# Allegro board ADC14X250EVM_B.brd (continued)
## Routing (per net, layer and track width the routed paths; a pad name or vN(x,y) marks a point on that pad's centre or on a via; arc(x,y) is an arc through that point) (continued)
GND2: length 14.7
  TOP w0.305: U7.3 16.79,7.83 v1(16.46,8.16)
  TOP w0.381: v1(27.44,12.36) 27.44,12.36 C86.2 C158.2 ; v1(24.68,13.48) 24.56,13.6 C84.2 ; v1(28.97,7.07) 28.55,7.07 28.37,7.25 J9.5 28.37,8.86 28.49,8.98 v1(28.95,8.98)
  BOTTOM w0.381: U6.25 20.2,13.42 v1(19.87,13.75) 19.55,13.42 U6.26 ; U6.21 22.8,10.94 v1(22.77,10.91) 22.61,10.76 C161.2 ; v1(24.68,13.48) 24.75,13.42 U6.18 ; U6.7 v1(22.15,17.76)
  BOTTOM w0.457: C162.2 v1(20.25,22.42)
  vias: v1(6.93,11.35) v1(8.34,10.82) v1(8.35,9.51) v1(10.34,10.85) v1(10.36,9.61) v1(11.46,10.95) v1(11.46,10.22) v1(12.74,10.97) v1(12.74,10.24) v1(15.82,8.18) v1(18.88,14.09) v1(20.82,14.11) v1(21.59,8.84) v1(21.62,7.05) v1(21.62,3.32) v1(21.65,1.53) v1(23.01,8.86) v1(23.02,7.04) v1(23.03,3.34) v1(23.05,1.52) v1(26.51,1.88) v1(30.51,8.84) v1(30.53,7.05) v1(30.52,3.37) v1(30.55,1.57) v1(31.92,8.86) v1(31.94,7.05) v1(31.93,3.38) v1(31.95,1.57) v2(0.91,22.91) v2(0.91,17.83) v2(0.91,12.75) v2(0.91,7.67) v2(0.91,2.59) v2(3.45,22.91) v2(5.83,12.74) v2(5.99,22.91) v2(5.99,17.83) v2(8.53,22.91) v2(11.07,22.91) v2(11.07,17.83) v2(11.07,2.59) v2(11.97,16.38) v2(11.97,15.16) v2(12.45,22.86) v2(12.45,21.97) v2(12.67,16.38) v2(12.67,15.16) v2(13.03,22.43) v2(13.61,22.91) v2(13.72,21.97) v2(13.96,3.85) v2(16.15,22.91) v2(16.15,17.83) v2(16.15,2.59) v2(22.1,15.32) v2(26.75,22.91) v2(27.18,15.32) v2(28.09,22.91) v2(30.56,22.91) v2(33.1,22.91) v2(33.53,20.4) v2(33.53,17.86) v2(33.53,15.32) v2(33.53,12.78) v2(33.53,10.24) v2(33.53,7.7) v2(33.53,5.16) v2(33.53,2.62)
VIN+: length 1.8
  TOP w0.203: U1.3 44.88,78.86 44.87,78.87 R24.2
VIN-: length 1.8
  TOP w0.203: U1.4 44.88,78.36 44.87,78.34 R25.2
VINN: length 2
  TOP w0.33: R15.2 R4.2 9.78,77.34 T1.4
VINN+: length 20.2
  TOP w0.203: R7.1 43,78.87 R24.1
  TOP w0.33: R7.1 42.82,79.1 42.3,79.63 arc(42.19,79.7) 42.07,79.72 C17.1 39.29,79.71 arc(38.99,79.65) 38.74,79.48 38.49,79.24 C19.1 38.11,79.11 arc(37.87,79.16) 37.67,79.3 37.47,79.5 arc(37.05,79.78) 36.56,79.88 R3.2
VINN-: length 20.2
  TOP w0.203: R9.1 43,78.34 R25.1
  TOP w0.33: R9.1 42.82,78.11 42.3,77.58 arc(42.19,77.51) 42.07,77.49 C23.1 arc(39,77.55) 38.73,77.72 38.49,77.97 C19.2 38.22,78.1 arc(37.89,78.03) 37.61,77.85 37.54,77.77 arc(37.05,77.45) 36.48,77.34 R10.2
VINP: length 2
  TOP w0.33: T1.6 9.78,79.88 R14.1 R11.2
ADC_CSB: length 120.8
  TOP w0.203: v3(57.4,96.27) 57.52,92.14 53.42,88.04 53.42,81.06 51.71,79.35 51.22,79.35 U1.23 ; R85.1 24.8,22.24 R83.1 v1(28.47,29.84)
  BOTTOM w0.203: R95.2 58.31,95.63 57.88,96.06 57.61,96.06 v3(57.4,96.27) 56.39,95.25 47.88,95.25 47.5,95.63 R77.2 47.37,95.58 46.53,94.74 42.04,94.74 30.81,83.52 30.8,83.52 29.18,81.89 28.59,81.89 26.06,79.36 26.06,69.7 29.2,66.56 29.2,30.58 v1(28.47,29.84)
ADC_SCLK: length 31.1
  TOP w0.203: U1.24 51.5,79.86 52.83,81.18 52.83,95.26 v3(54.98,97.41)
  BOTTOM w0.203: R92.2 58.88,97.46 58.51,97.82 56.42,97.82 56.01,97.41 v3(54.98,97.41) R70.2
ADC_SDI: length 30.8
  TOP w0.203: v3(51.27,98.42) 51.27,86.68 52.25,85.7 52.25,81.85 50.98,80.58 U1.25
  BOTTOM w0.203: R93.1 v3(51.27,98.42) R73.2
ADC_SDO: length 30.3
  TOP w0.203: U1.26 49.99,80.97 50.12,81.1 50.26,81.23 50.9,81.23 51.66,82 51.66,84.28 48.73,87.21 v3(48.73,96.39)
  BOTTOM w0.203: R94.1 58.88,96.44 58.06,97.26 56.74,97.26 55.88,96.39 v3(48.73,96.39) R72.2
BP2P5: length 25.5
  TOP w0.305: TP14.1 64.98,89.71 59.24,83.98 59.24,81.43 57.31,79.5 v1(57.28,79.5) C44.1 52.94,79.5 52.66,79.22 C43.1 52.15,79.22 51.78,78.86 U1.22
  BOTTOM w0.381: v1(57.28,79.5) 57.4,79.38 C45.1
CLKIN+: length 15.6
  TOP w0.203: v1(45.6,60.63) R18.2 45.79,61.41 45.79,62.88 46.56,63.64 46.56,74.57 46.99,75 U1.9
CLKIN-: length 15.6
  TOP w0.203: v1(46.31,60.63) R18.1 46.2,61.32 46.2,62.71 46.97,63.48 46.97,74.4 47.49,74.92 U1.10
CLKOUT2+: length 31.5
  TOP w0.203: U13.15 68.62,41.87 68.33,41.87 68.28,41.82 66.81,41.82 66.18,41.19 65.9,41.19 v1(65.71,41.38)
  BOTTOM w0.203: C71.1 46.14,57.9 46.14,57 62.02,41.12 64.9,41.12 65.08,41.3 65.08,41.57 65.26,41.76 65.53,41.76 65.71,41.57 v1(65.71,41.38)
CLKOUT2-: length 31.5
  TOP w0.203: U13.16 68.62,41.36 68.33,41.36 68.28,41.41 66.98,41.41 66.35,40.78 65.88,40.78 v1(65.71,40.62)
  BOTTOM w0.203: v1(65.71,40.62) 65.61,40.72 61.85,40.72 45.74,56.83 45.74,57.92 C70.1
CLKOUT3+: length 31.5
  TOP w0.203: v1(65.71,43.61) 65.88,43.45 66.35,43.45 66.98,42.82 68.28,42.82 68.31,42.86 68.62,42.86 U13.13
  BOTTOM w0.203: C69.1 49.56,57.89 49.56,57.33 49.89,57 53.75,57 54.19,56.56 54.19,55.33 53.75,54.89 52.88,54.89 52.55,54.56 52.55,53.62 62.82,43.36 64.94,43.36 65.08,43.5 65.08,43.79 65.26,43.98 65.54,43.98 65.71,43.81 v1(65.71,43.61)
CLKOUT3-: length 31.5
  TOP w0.203: U13.14 68.62,42.37 68.31,42.37 68.28,42.41 66.81,42.41 66.18,43.04 65.9,43.04 v1(65.71,42.85)
  BOTTOM w0.203: C68.1 49.15,57.94 49.15,57.16 49.72,56.59 53.58,56.59 53.78,56.39 53.78,55.5 53.58,55.3 52.71,55.3 52.14,54.73 52.14,53.46 62.65,42.95 65.61,42.95 v1(65.71,42.85)
CLKOUT4+: length 1.8
  TOP w0.203: v1(72.63,39.05) 72.81,39.23 72.81,40.38 72.76,40.43 72.76,40.72 U13.24
CLKOUT4-: length 1.8
  TOP w0.203: U13.25 73.27,40.72 73.27,40.43 73.22,40.38 73.22,39.23 v1(73.39,39.05)
CLKOUT8+: length 3.5
  TOP w0.203: R165.1 76.72,52.36 76.72,51.63 75.72,50.62 75.72,49.85 75.76,49.82 75.76,49.51 U13.51
CLKOUT8-: length 3.5
  TOP w0.203: U13.52 75.27,49.51 75.27,49.82 75.31,49.85 75.31,50.79 76.31,51.79 76.31,52.33 R164.1
CLKOUT10+: length 3.5
  TOP w0.203: R163.1 74.22,52.75 74.22,49.85 74.26,49.82 74.26,49.51 U13.54
CLKOUT10-: length 3.5
  TOP w0.203: U13.55 73.77,49.51 73.77,49.82 73.81,49.85 73.81,52.75 R162.1
CLKOUT11+: length 3.5
  TOP w0.203: R161.1 72.21,52.33 72.21,51.79 73.22,50.79 73.22,49.85 73.27,49.8 73.27,49.51 U13.56
CLKOUT11-: length 3.5
  TOP w0.203: R160.1 71.81,52.36 71.81,51.63 72.81,50.62 72.81,49.85 72.76,49.8 72.76,49.51 U13.57
CSB_LMK_3P3: length 24.3
  TOP w0.203: U13.18 69.76,40.72 69.76,39.67 67.31,37.22 67.31,23.11 64.44,20.24 R57.2
EXT_CLK+: length 14.1
  TOP w0.203: R40.1 45.76,59.45 45.76,57.04 41.09,52.38 41.09,51.51 40.05,50.46 T3.4
EXT_CLK-: length 14.1
  TOP w0.203: R41.1 46.16,59.47 46.16,56.88 41.5,52.21 41.5,51.58 42.59,50.49 T3.6
EXT_REF: length 34.3
  TOP w0.33: R35.2 R34.1 80.09,5.21 81.43,3.87 J7.1
EXT_SYSREF+: length 14.1
  TOP w0.203: R44.1 49.17,59.47 49.17,56.95 53.82,52.29 53.82,51.73 52.75,50.65 T4.4
EXT_SYSREF-: length 14.1
  TOP w0.203: R45.1 49.57,59.45 49.57,57.12 54.23,52.46 54.23,51.5 55.29,50.44 T4.6
EXTREF: length 35.3
  TOP w0.33: R17.2 v1(46.35,35.73)
  BOTTOM w0.33: R227.2 78.23,35.76 75.87,33.4 62.23,33.4 60.54,35.09 46.99,35.09 v1(46.35,35.73)
EXTREF_XO: length 5.9
  TOP w0.33: v1(80.09,35.73) C159.1 R36.2
  BOTTOM w0.33: v1(80.09,35.73) 80,35.81 R227.1
EXTXO:
  vias: v1(81.11,35.73)
FMC_FPGA_DEVCLKA+: length 83.9
  TOP w0.203: v1(109.21,93.6) 109.31,93.7 109.31,94.49 109.9,95.07 116.24,95.07 119.91,91.41 119.91,79.24 117.5,76.83 115.08,74.42 91.43,74.42 76.71,59.7 76.71,53.72 R165.2
  BOTTOM w0.203: J8.D4 v1(109.21,93.6)
FMC_FPGA_DEVCLKA-: length 83.9
  TOP w0.203: v1(110.48,93.6) 110.48,93.37 110.28,93.17 109.9,93.17 109.72,93.34 109.72,94.32 110.07,94.67 116.07,94.67 119.5,91.24 119.5,79.41 114.92,74.83 91.26,74.83 76.3,59.87 76.3,53.72 R164.2
  BOTTOM w0.203: J8.D5 v1(110.48,93.6)
FMC_FPGA_DEVCLKB+: length 83.4
  TOP w0.203: v1(105.4,92.33) 106.97,92.33 107.51,91.79 107.51,89.66 107.82,89.36 116.4,89.36 118.27,87.48 118.27,80.42 114.79,76.94 91.28,76.94 73.34,58.99 73.34,55.63 74.22,54.74 74.22,54.12 R163.2
  BOTTOM w0.203: J8.G6 v1(105.4,92.33)
FMC_FPGA_DEVCLKB-: length 83.4
  TOP w0.203: v1(105.4,91.06) 105.4,91.57 105.76,91.92 106.8,91.92 107.11,91.62 107.11,89.49 107.65,88.95 116.23,88.95 117.87,87.32 117.87,80.59 114.62,77.34 91.11,77.34 72.93,59.16 72.93,55.46 73.81,54.58 73.81,54.12 R162.2
  BOTTOM w0.203: J8.G7 v1(105.4,91.06)
FMC_FPGA_SYSREF+: length 83.4
  TOP w0.203: R161.2 72.22,53.72 72.22,54.19 71.66,54.75 69.48,54.75 69.28,54.94 69.28,55.84 69.48,56.04 71.22,56.04 71.79,56.61 71.79,60.07 91.32,79.6 115.27,79.6 116.33,80.65 116.33,87.25 115.79,87.78 110.76,87.78 109.54,86.56 106.56,86.56 106.25,86.87 106.25,87.12 106.38,87.25 v1(106.67,87.25)
  BOTTOM w0.203: v1(106.67,87.25) J8.G9
FMC_FPGA_SYSREF-: length 83.4
  TOP w0.203: R160.2 71.82,53.72 71.82,54.02 71.49,54.34 69.31,54.34 68.87,54.78 68.87,56.01 69.31,56.44 71.05,56.44 71.38,56.77 71.38,60.24 91.15,80.01 115.11,80.01 115.92,80.82 115.92,87.08 115.62,87.38 110.93,87.38 109.71,86.16 106.39,86.16 105.85,86.7 105.85,87.08 105.68,87.25 v1(105.4,87.25)
  BOTTOM w0.203: J8.G10 v1(105.4,87.25)
LMK_ADC_DEVCLK+: length 0.7
  BOTTOM w0.203: R43.1 45.44,59.46 C70.2
LMK_ADC_DEVCLK-: length 0.7
  BOTTOM w0.203: C71.2 46.46,59.46 R50.1
LMK_ADC_SYSREF+: length 0.7
  BOTTOM w0.203: C68.2 48.87,59.46 R51.1
LMK_ADC_SYSREF-: length 0.7
  BOTTOM w0.203: R61.1 49.89,59.46 C69.2
LMK_CSB: length 52.7
  TOP w0.203: U5.13 62.6,10.68 62.05,10.13 62,10.13 61.19,9.32 v2(57.43,9.32)
  BOTTOM w0.203: R75.2 23.28,25.26 24.56,26.54 25.53,26.54 ; v1(25.53,25.91) 25.53,26.54 ; 25.53,26.54 35.46,26.54 40.74,21.26 41.48,21.26 50.88,11.86 54.89,11.86 v2(57.43,9.32)
LMK_DIR: length 51.5
  TOP w0.203: R74.2 22.53,22.68 v1(22.53,29.08)
  TOP w0.254: v2(60.65,18.85) U5.7
  BOTTOM w0.203: v1(22.53,29.08) 37.8,29.08 48.67,18.21 59.71,18.21 59.84,18.35 R27.2 60.65,18.67 v2(60.65,18.85)
LMK_RESET: length 15.2
  TOP w0.203: U13.5 68.09,46.87 v2(67.99,46.97) ; R112.2 v2(64.08,35.92)
  BOTTOM w0.203: R113.2 v2(64.08,35.92) 64.08,37.62 66.8,40.34 66.8,45.92 67.85,46.97 v2(67.99,46.97)
LMK_RESET_FMC: length 71
  TOP w0.203: v1(105.4,68.2) 104.77,67.56 v2(95.25,67.56)
  BOTTOM w0.203: v2(95.25,67.56) 95.25,40.16 91.77,36.68 78.26,36.68 76.89,35.31 68.07,35.31 67.79,35.03 R113.1
  BOTTOM w0.508: J8.G24 v1(105.4,68.2)
LMK_SCLK: length 54.8
  TOP w0.254: v2(61.3,12.9) U5.11
  BOTTOM w0.203: v2(61.3,12.9) 61.3,13.88 60.67,14.52 49.57,14.52 36.27,27.81 21.08,27.81 18.73,25.46 R71.2
LMK_SDIO: length 48.7
  TOP w0.203: v2(55.5,9.32) 56.24,10.06 61.09,10.06 61.95,10.92 U5.12
  BOTTOM w0.203: R76.2 24.04,23.25 26.06,25.27 34.97,25.27 40.51,19.74 41.25,19.74 41.91,19.08 41.91,18.34 42.6,17.65 44.2,17.65 51.31,10.54 52.4,10.54 53.62,9.32 v2(55.5,9.32)
LMK_SYNC: length 13
  TOP w0.203: U13.6 68.1,46.37 v2(67.99,46.26) ; v2(65.3,35.92) v2(65.3,36.8)
  BOTTOM w0.203: v2(67.99,46.26) 67.39,45.66 67.39,38.89 v2(65.3,36.8) v2(65.3,35.92)
LMK_SYNC_FMC: length 67.9
  TOP w0.203: v1(105.4,66.93) 104.77,66.29 v2(94.44,66.29)
  BOTTOM w0.203: R114.1 76.85,35.92 78.37,37.44 91.36,37.44 94.44,40.51 v2(94.44,66.29)
  BOTTOM w0.508: J8.G25 v1(105.4,66.93)
LMK_VCC1/5/6: length 5.3
  TOP w0.203: 77.72,41.36 77.72,41.36 U13.33 ; v2(67.99,44.46) 68.09,44.36 68.62,44.36 U13.10 ; U13.36 77.41,42.86
  TOP w0.254: v2(77.98,41.33) 77.96,41.36 77.72,41.36 ; 77.41,42.86 v1(77.98,42.86)
  BOTTOM w0.381: L3.1 68.47,45.68 C118.1 C61.1 v2(67.99,44.46) ; v2(77.98,41.33) C160.1 ; v1(77.98,42.86) C199.1
LMK_VCC2: length 1.9
  TOP w0.203: U13.17 69.25,40.72 69.25,40.2 v2(69.15,40.09)
  BOTTOM w0.381: v2(69.15,40.09) C152.1
  BOTTOM w0.559: v2(69.15,40.09) 69.15,39.51 L4.2
LMK_VCC3: length 2.1
  TOP w0.203: U13.21 71.26,40.72 71.26,40.2 v2(71.36,40.09)
  BOTTOM w0.381: C200.1 v2(71.36,40.09)
  BOTTOM w0.559: L9.2 70.79,39.52 v2(71.36,40.09)
LMK_VCC4: length 2.5
  TOP w0.203: 73.77,40.72 U13.26
  TOP w0.254: v2(73.8,40.15) 73.77,40.17 73.77,40.72
  BOTTOM w0.381: v2(73.8,40.15) C201.1
  BOTTOM w0.559: v2(73.8,40.15) 74.04,40.39 L10.2
LMK_VCC7: length 2
  TOP w0.203: v1(77.98,44.36) 77.41,44.36 U13.39
  BOTTOM w0.381: L13.2 78.82,44.36 v1(77.98,44.36) C206.1
LMK_VCC8/10: length 9.4
  TOP w0.203: U13.42 77.41,45.88 ; U13.47 77.41,48.37
  TOP w0.254: 77.41,48.37 v1(77.98,48.37) ; 77.41,45.88 v1(77.98,45.88)
  L4_GND w0.559: v1(77.98,48.37) 78.69,47.66 78.69,46.58 v1(77.98,45.88)
  BOTTOM w0.381: C141.1 C204.1 v1(77.98,45.88) 78.82,45.88 L13.1 ; L5.1 77.98,49.51 v1(77.98,48.37) ; L14.1 78.66,48.37 v1(77.98,48.37) ; C164.1 v1(77.98,48.37)
LMK_VCC9: length 2
  TOP w0.203: v1(77.98,47.35) 77.97,47.37 U13.45
  BOTTOM w0.381: L14.2 78.66,47.35 v1(77.98,47.35) C205.1
LMK_VCC11: length 1.8
  TOP w0.254: U13.53 v1(74.76,50.01)
  BOTTOM w0.381: C202.1 v1(74.76,50.01) 75.41,50.66 L11.2
LMK_VCC12: length 2.4
  TOP w0.203: U13.64 69.25,49.51
  TOP w0.254: 69.25,49.51 v2(69.25,50.09)
  BOTTOM w0.381: C203.1 v2(69.25,50.09)
  BOTTOM w0.559: L12.2 68.1,50.09 v2(69.25,50.09)
PG_C2M: length 14
  TOP w0.203: v1(98.17,101.09) R155.1
  BOTTOM w0.203: v1(98.17,101.09) 100.58,101.09 102.36,99.31 108.58,99.31 J8.D1
PG_M2C: length 10.7
  TOP w0.203: v1(106.68,98.67) 106.04,99.31 R156.2
  BOTTOM w0.203: J8.F1 v1(106.68,98.67)
REFCLK: length 26.9
  TOP w0.33: T5.1 70.47,5.62 68.73,3.87 J6.1
REFCLK+: length 6
  TOP w0.203: C81.2 72.63,35.71 70.47,33.55 T5.6
REFCLK-: length 6
  TOP w0.203: C80.2 73.39,35.71 75.55,33.55 T5.4
SCLK_LMK_3P3: length 28.7
  TOP w0.203: v2(67.94,22.78) 67.94,37.09 70.27,39.41 70.27,40.72 U13.19
  BOTTOM w0.203: v2(67.94,22.78) 67.94,24.54 67.39,25.1 64.72,25.1 62.41,22.78 v2(61.07,22.78)
SDIO_LMK_3P3: length 26.7
  TOP w0.203: v2(68.58,21.51) 68.58,36.96 70.75,39.13 70.75,40.72 U13.20
  BOTTOM w0.203: v2(61.95,21.51) v2(68.58,21.51)
SO+: length 53.5
  TOP w0.203: C37.2 67.27,77.38 81.75,77.38 97.62,93.26 107.97,93.26 109.49,91.73 110.71,91.73 110.91,91.53 110.91,90.89 110.79,90.77 110.49,90.77 110.45,90.81 110.45,91.02 v1(110.48,91.06)
  BOTTOM w0.203: J8.C6 v1(110.48,91.06)
SO-: length 53.5
  TOP w0.203: C36.2 67.27,77.79 81.58,77.79 97.45,93.66 108.14,93.66 109.66,92.14 110.88,92.14 111.32,91.7 111.32,91.31 111.57,91.06 v1(111.75,91.06)
  BOTTOM w0.203: J8.C7 v1(111.75,91.06)
SSYSREF+: length 10.9
  TOP w0.203: C186.2 48.87,70.93 49.04,70.76 49.04,65.69 49.55,65.19 49.55,62.96 49.18,62.59 49.18,61.37 R29.2 v1(49.02,60.63)
SSYSREF-: length 10.9
  TOP w0.203: C187.2 49.62,70.93 49.45,70.76 49.45,65.86 49.96,65.35 49.96,62.79 49.59,62.42 49.59,61.36 R29.1 v1(49.74,60.63)
STATUS_LD1: length 18.9
  TOP w0.203: TP19.1 77.37,23.43 77.37,34.52 75.9,35.99 75.9,40.01 76.26,40.37 76.26,40.72 U13.31
STATUS_LD2: length 5.9
  TOP w0.203: U13.48 77.41,48.88 77.45,48.88 77.83,49.25 77.83,50.52 79.45,52.15 TP18.1
SYNCB+: length 67
  TOP w0.203: v1(105.4,83.44) 105.19,83.44 105.07,83.32 105.07,83.09 105.17,83 106.07,83 106.46,83.39 106.46,84.67 105.99,85.14 92.19,85.14 81.02,73.97 50.51,73.97 50.04,74.44 50.04,75.18 49.99,75.23 U1.15
  BOTTOM w0.203: J8.G12 v1(105.4,83.44)
SYNCB-: length 67
  TOP w0.203: v1(105.4,82.17) 105.4,82.41 105.58,82.59 106.24,82.59 106.87,83.22 106.87,84.83 106.16,85.55 92.02,85.55 80.85,74.38 50.67,74.38 50.45,74.61 50.45,75.18 50.49,75.23 U1.16
  BOTTOM w0.203: J8.G13 v1(105.4,82.17)
SYSREF+: length 3.9
  TOP w0.203: C186.1 48.87,72.24 49.01,72.39 49.01,72.83 49.01,74.77 48.99,74.79 U1.13
SYSREF-: length 3.9
  TOP w0.203: C179.1 49.62,72.24 49.47,72.39 49.47,72.64 49.47,74.77 49.49,74.79 U1.14
T1+: length 1.5
  TOP w0.33: C20.1 T1.1
T1-: length 1.5
  TOP w0.33: C21.1 T1.3
V_VCXO3.3: length 58.4
  TOP w0.559: 90.27,57.62 v2(90.27,57.09) v2(88.29,57.09) 88.29,57.62 ; 90.27,57.62 v2(90.27,58.15) v2(88.29,58.15) 88.29,57.62 ; 90.27,57.62 88.29,57.62 ; 88.29,57.62 C60.1 v2(86.64,57.62) ; TP8.1 Z10.3 v2(92.05,28.97)
  L3_POWER w0.559: 88.29,57.62 v2(86.64,57.62) ; 88.29,57.62 v2(88.29,57.09) v2(90.27,57.09) 90.27,57.62 ; 88.29,57.62 v2(88.29,58.15) v2(90.27,58.15) 90.27,57.62 ; 88.29,57.62 L8.1 90.27,57.62
  L3_POWER w1.27: L8.1 94.46,52.44 TP8.1
  BOTTOM w0.762: L8.1 v2(86.64,57.62)
  BOTTOM w1.27: Z10.3 TP8.1
  vias: v2(93.95,29.33) v2(93.95,28.62) v2(94.97,29.33) v2(94.97,28.62)
V_XO3.3: length 36.3
  TOP w0.559: v2(87.08,33.67) v2(87.08,31.6) 86.67,31.6 ; v2(87.08,33.67) v2(87.08,35.74) 86.67,35.74 ; v2(87.08,33.67) Y1.6 ; 86.67,35.74 v2(86.27,35.74) v2(86.27,33.67) ; 86.67,35.74 Y1.6 ; 86.67,31.6 v2(86.27,31.6) v2(86.27,33.67) ; 86.67,31.6 Y1.6 ; v2(86.27,33.67) Y1.6 ; v2(83.24,17.85) Z9.3
  TOP w1.016: v2(86.27,31.6) 85.66,30.99 v1(85.66,22.9) TP7.1 Z9.3
  BOTTOM w0.381: v1(85.66,22.9) TP7.1
  BOTTOM w1.27: TP7.1 Z9.3
  vias: v2(85.15,18.2) v2(85.15,17.5) v2(86.16,18.2) v2(86.16,17.5)
VA1.2: length 89.2
  TOP w0.102: C99.1 45.94,100.85
  TOP w0.254: v1(43.85,76.67) 43.9,76.67 44.29,76.28 45.02,76.28 45.59,76.85 U1.7
  TOP w0.305: C10.1 49.83,81.97 48.99,81.12 U1.28
  TOP w0.381: v1(49.83,83.74) 49.86,83.72 C9.1 49.86,82.02 C10.1
  TOP w0.635: v1(41.4,75.56) 42.11,75.56 42.29,75.74 C12.1 42.71,75.77 43.24,76.3 43.44,76.3 43.8,76.67 v1(43.85,76.67)
  TOP w1.27: TP2.1 C104.1 Z4.3
  L4_GND w0.559: v2(47.66,100.49) v2(47.66,101.2) v2(48.68,101.2) v2(48.68,100.49) v2(47.66,100.49)
  L4_GND w0.635: v2(48.68,100.49) 48.68,98.77 50.55,96.9 50.55,88.8 49.28,87.53 49.28,84.3 v1(49.83,83.74) ; v2(47.66,100.49) 43.18,96.01 43.18,78.46 43.85,77.78 v1(43.85,76.67) 43.37,76.67 42.59,75.88 41.72,75.88 v1(41.4,75.56)
  BOTTOM w0.254: SW3.1 32.28,58.75 32.28,66.42 39.14,73.28 40.64,73.28 41.4,74.04 v1(41.4,75.56)
VA1.2_AUX: length 43.9
  TOP w0.102: C111.1 56.61,100.85
  TOP w0.254: 52.08,76.17 51.9,76.35 U1.17
  TOP w0.381: 52.08,76.17 C35.1 53.11,76.17 v1(53.47,75.82)
  TOP w1.27: TP3.1 C112.1 Z5.3
  L4_GND w0.559: 59.35,100.85 v2(59.35,101.2) v2(58.33,101.2) v2(58.33,100.49) v2(59.35,100.49) 59.35,100.85 ; 59.35,100.85 58.88,100.85
  L4_GND w0.635: v2(59.35,100.49) 59.35,89.08 60.34,88.09 60.34,84.3 58.54,82.5 58.54,79.75 54.61,75.82 v1(53.47,75.82) ; 58.33,100.85 58.88,100.85
  BOTTOM w0.381: 54.48,76.07 53.72,76.07 v1(53.47,75.82)
VA1.8: length 205.1
  TOP w0.254: C24.1 48.49,74.87 48.49,74.87 U1.12
  TOP w0.305: C13.1 49.05,81.86 48.49,81.31 U1.29 ; v1(48.51,72.96) C18.1 48.49,73.69 C24.1 ; C8.1 46.86,81.19 46.99,81.06 U1.32
  TOP w0.381: C13.1 49.17,82.12 v1(49.17,82.96) 49.17,83.24 v1(48.79,83.62) ; v1(46.56,83.67) 46.48,83.59 v1(46.48,82.93) 46.48,82.37 C8.1
  TOP w0.457: R83.2 v1(27.05,25.91)
  TOP w0.559: v2(10.97,50.47) Z6.3
  TOP w1.27: Z6.3 13.67,48.06 TP4.1
  L3_POWER w0.635: v1(49.17,82.96) 48.79,83.34 v1(48.79,83.62)
  L4_GND w0.635: v1(27.05,25.91) 17.23,35.73 17.23,40.55 16.29,41.49 16.29,45.53 14.26,47.57 14.26,48.02 ; 14.26,48.02 17.76,48.02 33.06,63.32 40.21,63.32 43.77,66.88 43.77,70.6 45.39,72.22 46.4,72.22 47.13,72.96 v1(48.51,72.96) ; 14.26,48.02 TP4.1 13.94,48.61 ; v1(46.56,83.67) 46.56,83.02 46.35,82.82 46.35,77.47 45.89,77 45.62,77 44.65,76.03 44.65,75.2 43.36,73.91 36.78,73.91 24.67,61.8 23.91,61.8 13.57,51.46 13.57,48.99 13.94,48.61 ; v1(48.79,83.62) 51.28,81.13 51.28,76.28 48.83,73.83 47.46,73.83 47.38,73.9 45.53,73.9 43.56,71.92 42.13,71.92 41.78,72.26 37.6,72.26 13.94,48.61
  BOTTOM w1.27: C115.1 13.67,48.06 TP4.1
  vias: v2(10.61,48.56) v2(10.61,47.55) v2(11.32,48.56) v2(11.32,47.55)
VA3.0: length 196.3
  TOP w0.254: v1(43.85,80.54) 44.25,80.54 C2.1 45.12,80.11 45.38,79.86 U1.1
  TOP w0.305: v1(43.85,81.43) v1(43.85,80.54)
  TOP w0.559: v2(10.97,63.17) Z7.3
  TOP w1.27: Z7.3 13.67,60.76 TP5.1
  L3_POWER w0.381: v1(91.44,64.52) 91.44,84.17 85.64,89.96 76.18,89.96 75.18,90.96 75.18,100.42 v2(74.19,101.41)
  BOTTOM w0.762: v2(74.19,101.41) 74.19,102.46 72.52,104.14 64.64,104.14 63.63,105.16 42.16,105.16 41.4,104.39 28.07,104.39 11.91,88.24 11.91,64.12 v2(10.97,63.17) ; v2(7.41,37.19) 16.48,37.19 19.46,40.16 19.46,57.63 16.05,61.04 TP5.1
  BOTTOM w1.27: Z7.3 13.67,60.76 TP5.1
  vias: v2(10.61,61.26) v2(10.61,60.25) v2(11.32,61.26) v2(11.32,60.25)
VADJ: length 77
  TOP w0.203: R156.1 95.81,99.31
  TOP w0.508: 95.81,99.31 v2(94.74,99.31) ; R42.1 96.01,47.65 97.16,46.51 v2(100.23,46.51) 102.76,46.51 v1(105.4,49.15) v1(106.67,49.15) v1(107.94,49.15) v1(109.21,49.15)
  BOTTOM w0.508: J8.H40 v1(105.4,49.15) ; J8.F40 v1(107.94,49.15) ; J8.E39 v1(109.21,49.15) ; J8.G39 v1(106.67,49.15)
  BOTTOM w0.635: v2(100.23,46.51) 100.23,47.23 100.19,47.27 100.19,96.79 97.66,99.31 v2(94.74,99.31)
VCM: length 28.1
  TOP w0.381: v1(41.81,78.61) R7.2 ; v1(41.81,78.61) C22.1 ; v1(41.81,78.61) R9.2
  BOTTOM w0.33: v1(26.59,78.61) 26.59,77.72 27.76,76.56 27.76,71.93 TP15.1
  BOTTOM w0.381: R16.1 41.61,78.41 41.08,77.88 C32.1 37.9,77.88 37.31,77.29 34.87,77.29 31.11,73.53 31.11,71.88 TP15.1
  BOTTOM w0.508: R16.1 41.8,78.63 v1(41.81,78.61)
VCMODE: length 13.2
  TOP w0.254: U1.6 45.42,77.35
  TOP w0.305: 45.42,77.35 45.37,77.31 45.37,77.3 45.15,77.07 v1(44.68,77.07)
  BOTTOM w0.381: R16.2 42.7,78.71 43.48,78.71 C26.1 ; C26.1 43.56,77.39 43.77,77.19 44.07,77.19 44.1,77.16 44.59,77.16 v1(44.68,77.07) ; C26.1 43.56,80.08 43.57,80.09 43.64,80.02 44.07,80.02 44.37,80.33 44.37,80.76 44.31,80.83 45.47,81.99 C27.1
VIO_B_M2C: length 8.1
  TOP w0.508: v1(102.86,49.15) v1(101.59,47.88) 98.88,47.88 98.37,48.39 R42.2
  BOTTOM w0.508: J8.K40 v1(101.59,47.88) ; J8.J39 v1(102.86,49.15)
VLMK3.3: length 17.5
  TOP w0.381: U5.16 v1(65.53,11.89)
  TOP w0.559: v2(72.67,15.87) Z8.3 TP6.1
  BOTTOM w0.381: C93.1 v2(66.24,48.79)
  BOTTOM w0.559: L12.1 69.01,47.75 L3.2 ; L4.1 v2(70.79,38)
  BOTTOM w0.762: v2(66.24,48.79) C92.1 v2(67.84,48.79) L12.1 ; v2(76.83,50.67) 77.37,51.21 v2(77.62,51.21) L5.2
  BOTTOM w1.27: Z8.3 TP6.1
  vias: v2(57.75,11.89) v2(74.57,16.22) v2(74.57,15.51) v2(75.08,38.96) v2(75.59,16.22) v2(75.59,15.51)
VN: length 10.2
  TOP w0.33: R5.1 7.25,77.21 arc(6.89,77.14) 6.58,76.93 arc(6.37,76.62) 6.3,76.26 6.3,73.14 arc(6.25,72.89) 6.11,72.68 arc(5.78,72.46) 5.4,72.38 J3.1
VP: length 10.2
  TOP w0.33: R12.1 6.99,80 arc(6.73,80.05) 6.5,80.2 arc(6.33,80.46) 6.27,80.77 6.27,83.86 arc(6.2,84.21) 6,84.51 arc(5.65,84.75) 5.23,84.83 J2.1
VSPI1.8: length 70.2
  TOP w0.254: U5.15 63.9,10.9 v2(63.93,10.87)
  TOP w0.381: v2(63.93,10.87) 63.96,10.84 C83.2
  TOP w0.559: v2(26.94,21.93) v2(26.38,21.93) v2(25.82,21.93) ; Z3.3 v2(6.93,12.62)
  TOP w1.27: TP20.1 Z3.3
  BOTTOM w0.381: U6.4 v2(20.2,20.43) 20.2,20.86 C162.1 ; R60.2 v2(25.82,21.93)
  BOTTOM w0.559: v2(63.93,10.87) 63.93,9.88 60.45,6.4 37.41,6.4 35.66,8.15 35.66,21.21 34.94,21.93 v2(26.94,21.93) v2(26.38,21.93) v2(25.82,21.93)
  BOTTOM w1.016: Z3.3 v2(6.93,12.62)
  BOTTOM w1.27: TP20.1 Z3.3
  vias: v2(8.84,12.97) v2(8.84,12.26) v2(9.86,12.97) v2(9.86,12.26)
N17161280: length 10.1
  TOP w0.508: 6.14,56.52 C132.1 ; 6.14,56.52 U10.5 ; 6.14,56.52 C129.1 4.71,56.39 3.34,56.39 R78.2
  TOP w0.762: R56.2 Z7.1
  TOP w1.27: C132.1 Z7.1
N17161284: length 2.5
  TOP w0.254: R97.1 R96.2 U10.8
N17161345: length 4.1
  TOP w0.254: R69.1 R78.1 4.71,55.07 C129.2
  TOP w0.508: U10.6 C129.2
N17161357: length 1.2
  TOP w0.305: U10.1 C131.1
N17161499: length 59.1
  TOP w0.508: R80.2 90.23,10.22 90.23,11.6 C142.1 90.1,13.02 ; 90.1,13.02 U11.5 ; 90.1,13.02 C145.1
  TOP w0.559: v2(85.15,12.67) 85.3,12.67 Z9.1 ; v2(86.16,12.67) 86.01,12.67 ; 86.01,12.67 85.85,12.67 v2(85.15,13.38) 85.3,13.38 Z9.1 ; 86.01,12.67 Z9.1
  TOP w1.27: C145.1 Z9.1
  L4_GND w0.559: 85.15,13.02 Z9.1 ; 85.15,13.02 v2(85.15,12.67) v2(86.16,12.67) ; 85.15,13.02 v2(85.15,13.38) ; 86.16,13.02 v2(86.16,13.38) ; 93.95,24.15 v2(93.95,24.5) v2(94.97,24.5) 94.97,24.15 ; 93.95,24.15 Z10.1 94.97,24.15 ; 93.95,24.15 v2(93.95,23.79) v2(94.97,23.79) 94.97,24.15
  L4_GND w1.27: Z10.1 96.09,22.52 96.09,13.82 94.79,12.52 88.41,12.52 87.91,13.02 Z9.1
  BOTTOM w0.559: 74.57,11.04 75.59,11.04 ; 74.57,11.04 v2(74.57,10.69) v2(75.59,10.69) 75.59,11.04 ; 74.57,11.04 v2(74.57,11.39) v2(75.59,11.39) 75.59,11.04 ; 85.72,13.38 v2(86.16,13.38) v2(86.16,12.67) v2(85.15,12.67) 85.15,13.13
  BOTTOM w1.27: 85.72,13.38 v2(85.15,13.38) 85.15,13.13 85.12,13.1 85.12,12.86 83.44,11.18 75.81,11.18 v2(75.59,11.39)
N17161629: length 2.7
  TOP w0.203: U11.8 R81.2 R82.1
N17161669: length 4.1
  TOP w0.254: C142.2 91.54,11.6 R80.1 R79.1
  TOP w0.508: U11.6 C142.2
N17161679: length 1.2
  TOP w0.305: U11.1 C144.1
N17161879: length 34.7
  TOP w0.508: 67.56,100.14 v2(67.56,98.72) ; 67.56,100.14 C109.1 ; 67.56,100.14 U8.5
  TOP w0.762: D2.1 40.05,103 42.72,105.67 Z4.1
  TOP w1.27: C109.1 60.36,105.67 Z5.1 Z4.1
N17161936: length 3.4
  TOP w0.203: U8.8 C106.2
  TOP w0.254: C106.2 R89.2 R65.1
N17162041: length 82.9
  TOP w0.508: 6.14,43.82 U9.5 ; 6.14,43.82 C122.1 ; 6.14,43.82 C120.1 4.71,43.69 3.34,43.69 R67.2
  TOP w0.762: v1(20.32,63.07) 21.51,63.07 22.61,61.98 22.61,56.64 17.78,51.82 9.14,51.82 8.51,51.18 8.51,50.93 8.23,50.65 8.23,50.31 7.94,50.01 7.76,50.01 7.74,49.99 7.57,49.99 7.37,49.78 6.69,49.78 6.14,49.24 Z6.1 ; v1(30.1,102.49) 30.61,103 R62.2
  TOP w1.27: Z6.1 C122.1
  BOTTOM w0.762: v1(20.32,63.07) 19.38,64.01 19.38,91.77 v1(30.1,102.49)
N17162051: length 3.4
  TOP w0.254: U9.8 C119.2 R90.2 R68.2
N17162120: length 4.1
  TOP w0.254: C120.2 4.71,42.37 R67.1 R66.1
  TOP w0.508: U9.6 C120.2
N17162132: length 1.2
  TOP w0.305: U9.1 C121.1
N17162350: length 3
  TOP w0.203: R63.1 R64.1 v2(69.18,98.72)
  TOP w0.508: U8.6 v2(69.18,98.72)
N17162360: length 1.2
  TOP w0.305: U8.1 C108.1
N17167241: length 4.6
  TOP w0.203: J9.2 25.98,8.03 v1(25.98,10.93) C158.1
  BOTTOM w0.102: v1(25.98,10.93) 25.98,12.13 U6.16
N17167387: length 6.4
  TOP w0.508: C102.1 13.64,7.79 14.4,7.04 U7.1
  TOP w1.27: Z3.1 C102.1
N17167421: length 8.7
  TOP w0.305: U7.6 15.47,9.91 16.07,10.51 16.07,10.63 ; U7.4 16.79,9.91 16.07,10.63 ; 16.07,10.63 16.07,10.86
  TOP w1.27: C96.1 15.11,14.56 16.07,13.6 R157.2 16.07,10.86 16.07,10.86
N17167654: length 95
  BOTTOM w0.203: U6.1 18.25,20.38 17.97,20.66 17.97,29.09 22.53,33.66 22.53,73.51 22.28,73.76 22.28,81.1 38.58,97.41 R70.1
N17167656: length 95.2
  TOP w0.203: v1(21.26,26.54) v1(21.26,35.94)
  BOTTOM w0.203: U6.5 20.85,20.74 21.01,20.9 21.01,26.29 v1(21.26,26.54) ; v1(21.26,35.94) 21.26,74.65 20.98,74.93 20.98,81.71 37.7,98.42 R73.1
N17167658: length 95.5
  TOP w0.203: v1(19.55,25.15) v1(19.55,29.66)
  BOTTOM w0.203: R72.1 39.4,96.39 27.92,84.91 26.84,84.91 23.81,81.88 23.81,73.55 24.46,72.9 24.46,67.62 26.66,65.42 26.66,36.77 v1(19.55,29.66) ; v1(19.55,25.15) U6.3
N17167660: length 92.4
  TOP w0.203: v1(24.75,29.84) v1(24.75,23.04)
  BOTTOM w0.203: v1(24.75,29.84) 24.75,31.22 27.93,34.41 27.93,66.05 25.27,68.71 25.27,75.03 24.79,75.51 24.79,81.18 27.94,84.33 29.14,84.33 40.19,95.38 40.26,95.38 40.64,95.76 45.8,95.76 45.92,95.63 R77.1
  BOTTOM w0.254: v1(24.75,23.04) U6.11
N17167662: length 1.9
  BOTTOM w0.203: R71.1 18.9,20.74 U6.2
N17167664: length 1.9
  BOTTOM w0.254: U6.9 23.45,20.74 R75.1
N17167666: length 1.8
  BOTTOM w0.254: R76.1 24.1,20.86 U6.10
N17167668: length 1.9
  BOTTOM w0.254: v2(21.78,20.91) 21.78,20.79 21.5,20.51 U6.6
N17167775: length 4
  TOP w0.203: U5.6 61.3,21.47 R58.1
N17167777: length 2.7
  TOP w0.203: U5.5 R59.1
N17167779: length 1.5
  TOP w0.203: U5.4 62.6,18.99 R57.1
N17167819: length 4.6
  TOP w0.203: J9.3 26.76,8.04 v1(26.76,10.92) 26.76,10.93 C86.1
  BOTTOM w0.102: U6.15 26.76,12.13 v1(26.76,10.92)
N17168074: length 1.9
  TOP w0.381: C84.1 25.58,13.52 v1(25.59,13.52)
  BOTTOM w0.381: v1(25.59,13.52) 25.4,13.33 U6.17
N17168078: length 1.9
  BOTTOM w0.254: U6.12 25.4,20.74 R60.1
N17168092: length 2.9
  TOP w0.381: v1(24.58,7.1) 25.01,7.1 25.17,7.26 J9.1 25.17,8.87 25.04,9 v1(24.59,9)
  vias: v1(19.33,16.33) v1(19.33,15.58) v1(20.41,16.34) v1(20.4,15.6)
N17168106: length 6.6
  TOP w0.381: R158.2 19.82,9.12 20.43,9.72 20.53,9.72 20.54,9.73 v1(23.6,9.73)
  BOTTOM w0.381: U6.20 23.45,11.01 23.63,10.83 C161.1 23.63,9.76 v1(23.6,9.73)
N17215258: length 3.9
  TOP w0.33: v2(14.86,78.59) T1.2 T1.5
N17215302: length 1.5
  TOP w0.33: C20.2 T2.6
N17215394: length 7.7
  TOP w0.33: v2(17.86,78.59) T2.5 T2.2 R8.1
N17215600: length 1.9
  TOP w0.33: T2.1 R3.1
N17215624: length 1.5
  TOP w0.33: T2.4 C21.2
N17215642: length 1.9
  TOP w0.33: T2.3 R10.1
N17220421: length 3.4
  TOP w0.406: T3.2 v1(41.32,46.21) T3.5
N17225099: length 3.4
  TOP w0.406: T4.5 v1(54.02,46.21) T4.2
N17242573: length 15.2
  TOP w0.203: U1.20 51.77,77.85 51.82,77.81 66.2,77.81 C36.1
N17242594: length 15.3
  TOP w0.203: U1.19 51.77,77.35 51.82,77.4 66.16,77.4 C37.1
N17273940: length 6.3
  TOP w0.762: R158.1 18.49,9.76 Z1.3
  TOP w0.889: Z1.3 18.15,11.13 17.34,11.94 R157.1
N17303725: length 3.2
  TOP w0.203: LF2_C1.1 LF2_C2.1 78.72,47.86 77.41,47.86 U13.46
N17303875: length 14.8
  BOTTOM w0.203: R37.2 78.29,38.21 C63.1 89.62,40.68 Y3.1
N17303984: length 5.9
  BOTTOM w0.762: Y3.6 v2(90.12,51.32) 90.12,53.17 L8.2
N17304319: length 1.4
  TOP w0.203: LF2_R2.1 LF2_C2.2
N17304368:
  vias: v1(84.53,46.23)
N17304374: length 1.7
  TOP w0.203: C51.2 R39.2 R38.1
N17304410: length 3.9
  BOTTOM w0.381: R31.1 v1(86.67,23.79) Y1.1
N17304458: length 1.8
  TOP w0.203: U13.44 77.41,46.87 77.7,46.87 77.75,46.82 78.9,46.82 C66.2
N17304625: length 2.6
  TOP w0.203: U13.32 76.77,40.72 76.77,39.74 LF1_C1.1 LF1_C2.1
  vias: v2(78.29,39.64)
N17305040: length 2.6
  TOP w0.203: C51.1 v1(80.09,46.23) C67.1
  BOTTOM w0.203: R30.1 80.01,45.72 80.09,45.8 v1(80.09,46.23)
N17305042: length 1.8
  TOP w0.203: U13.43 77.41,46.36 77.7,46.36 77.75,46.41 78.9,46.41 C67.2
N17305088: length 1.8
  TOP w0.203: U13.35 77.69,42.37 77.7,42.37 77.75,42.32 78.9,42.32 C195.2
N17305090: length 3.3
  TOP w0.203: v1(79.79,41.74) 80.09,41.43 C159.2
  BOTTOM w0.203: v1(79.79,41.74) v1(79.79,43.24) 80.01,43.46 R30.2
N17305092: length 1.8
  TOP w0.203: U13.34 77.41,41.87 77.7,41.87 77.75,41.92 78.9,41.92 C196.2
N17305106: length 1.8
  TOP w0.203: U13.38 77.41,43.87 77.7,43.87 77.75,43.82 78.9,43.82 C197.2
N17305110: length 1.8
  TOP w0.203: C198.2 78.9,43.42 77.75,43.42 77.7,43.36 77.41,43.36 U13.37
N17305389: length 7.2
  TOP w0.203: SW2.2 59.92,30.96 60.99,30.96 R112.1
N17305438: length 5.2
  TOP w0.203: R115.1 SW1.2
N17320541: length 12.2
  TOP w0.203: U13.59 71.77,49.51 71.77,49.88 71.52,50.13 70.06,50.13 69.27,50.93 64.97,50.93 TP16.1
N17320545: length 11.7
  TOP w0.203: U13.58 72.25,49.51 72.25,50 71.58,50.67 70.31,50.67 69.52,51.46 TP17.1
N17320732: length 1
  TOP w0.203: U13.12 68.62,43.36
  TOP w0.254: 68.62,43.36 v1(68.04,43.36)
  BOTTOM w0.381: C47.1 v1(68.04,43.36)
N17320734: length 2.5
  TOP w0.203: U13.11 68.73,43.87 68.73,43.87 67.71,43.87 66.85,44.73 C48.1
N17329800: length 20.1
  BOTTOM w0.203: v1(48.16,71.77) 48.16,71.66 46.25,69.75 45.29,69.75 43.97,68.43 43.97,64.08 39.85,59.97 39.85,59.82 39.55,59.51 ; 39.55,59.51 40.03,59.03 R120.1 40.03,57.94 C87.2 ; 39.55,59.51 SW3.2
N17424784: length 0.9
  BOTTOM w0.508: J8.D31 v1(109.21,59.31)
N17424792: length 0.9
  BOTTOM w0.508: J8.D30 v1(109.21,60.58)
N17424855: length 9.8
  TOP w0.381: Q1.1 R102.2 98.11,58.72 103.54,58.72 v1(104.13,59.31)
  BOTTOM w0.381: J8.H31 v1(104.13,59.31)
N17425083: length 86.1
  TOP w0.203: v1(104.13,52.96) 103.5,53.59 v1(98.19,53.59)
  BOTTOM w0.203: v1(98.19,53.59) 98.19,89.15 95.55,91.8 92.3,91.8 90.83,90.32 79.98,90.32 72.9,97.41 69.98,97.41 69.34,96.77 61.7,96.77 61.06,97.41 R92.1
  BOTTOM w0.508: J8.H37 v1(104.13,52.96)
N17425085: length 86.4
  TOP w0.203: v1(104.13,50.42) 103.5,51.05 v1(96.56,51.05)
  BOTTOM w0.203: v1(96.56,51.05) 96.56,88.44 95.17,89.84 93.77,89.84 93.22,89.28 74.04,89.28 67.54,95.78 60.48,95.78 60.33,95.63 R95.1
  BOTTOM w0.508: J8.H38 v1(104.13,50.42)
N17425095: length 2.1
  TOP w0.305: SYNC.2 Q1.3
N17425908: length 87.4
  TOP w0.203: v1(99,54.86) 104.39,54.86 104.77,54.48 104.77,53.59 v1(105.4,52.96)
  BOTTOM w0.203: v1(99,54.86) 99,89.51 96,92.52 92.16,92.52 90.53,90.88 80.31,90.88 73.28,97.92 61.7,97.92 61.19,98.42 R93.2
  BOTTOM w0.508: J8.G36 v1(105.4,52.96)
N17425910: length 87.4
  TOP w0.203: v1(97.38,52.32) 104.77,52.32 v1(105.4,51.69)
  BOTTOM w0.203: v1(97.38,52.32) 97.38,88.8 94.93,91.25 92.9,91.25 91.52,89.87 74.47,89.87 68.05,96.29 60.43,96.29 60.33,96.39 R94.2
  BOTTOM w0.508: J8.G37 v1(105.4,51.69)
N17439983: length 1.3
  TOP w0.203: LF1_C2.2 LF1_R2.1
N17456786: length 38.6
  TOP w0.33: C28.1 R21.2 R22.1 40.05,6.48 40.43,6.1 J4.1
N17456846: length 38.6
  TOP w0.33: C53.1 R23.1 52.75,6.5 53.13,6.12 J5.1
N17469287: length 16.8
  TOP w0.33: R13.1 24.31,80.89 23.96,81.23 arc(23.49,81.55) 22.93,81.66 10.13,81.66 arc(9.76,81.59) 9.44,81.38 9.34,81.27 arc(9.06,81.08) 8.72,81.02 R1.1
N17469485: length 16.8
  TOP w0.33: R53.1 24.31,76.32 23.93,75.94 arc(23.49,75.64) 22.96,75.54 10.16,75.54 arc(9.81,75.61) 9.51,75.81 9.35,75.97 arc(9.1,76.13) 8.81,76.19 R5.2
N17474156: length 2.9
  TOP w0.203: T4.3 C53.2
N17474169: length 2.9
  TOP w0.203: T4.1 C55.2
N17474172: length 2.9
  TOP w0.203: T3.1 C29.2
N17474175: length 2.9
  TOP w0.203: T3.3 C28.2
N17476146: length 2.9
  TOP w0.33: R17.1 R19.1 R21.1
N17481569: length 1.9
  TOP w0.381: R87.2 R86.2 U5.9
N17576943: length 2.2
  TOP w0.762: 32.64,103 D2.2
N17577005: length 17.8
  TOP w0.762: R56.1 6.14,64.94 6.76,65.56 12.93,65.56 17.4,61.09 18.41,61.09 20.14,59.36 D1.2
N174249330: length 1.9
  TOP w0.305: R28.2 SYNC.1

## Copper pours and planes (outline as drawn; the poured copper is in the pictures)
+5V on BOTTOM: 89.92,22.1 89.92,17.02 91.82,17.02 91.82,22.1
+5V on L3_POWER: 88.04,0.64 88.04,5.71 34.46,5.71 34.46,23.84 0.64,23.84 0.64,66.66 5.85,66.66 5.85,90.58 0.76,90.58 0.76,106.68 93.83,106.68 93.83,81.76 98.68,81.76 98.68,39.91 97.15,39.91 97.15,0.64 ; 3 cut-outs
GND on TOP: 34.46,0.05 34.46,23.84 0.64,23.84 0.64,67.12 0.06,67.12 0.06,71.55 2.39,71.55 2.39,72.08 3.62,72.08 3.62,72.71 2.39,72.71 2.39,73.21 0.06,73.21 0.06,84 2.3,84 2.3,84.52 3.62,84.52 3.62,85.16 2.3,85.16 2.3,85.65 0.06,85.65 0.06,90.12 0.64,90.12 0.64,106.68 121.79,106.68 121.79,39.88 97.15,39.88 97.15,0.64 86.71,0.64 86.71,0.05 82.26,0.05 82.26,2.02 81.74,2.02 81.74,3.62 81.11,3.62 81.11,2.02 80.6,2.02 80.6,0.05 69.55,0.05 69.55,2.04 69.04,2.04 69.04,3.62 68.41,3.62 68.41,2.04 67.9,2.04 67.9,0.05 63.42,0.05 63.42,0.64 58.42,0.64 58.42,0.05 53.95,0.05 53.95,2.08 53.44,2.08 53.44,3.62 52.81,3.62 52.81,2.08 52.3,2.08 52.3,0.05 41.25,0.05 41.25,2.14 40.75,2.14 40.75,3.62 40.11,3.62 40.11,2.14 39.6,2.14 39.6,0.05 ; 5 cut-outs
GND on BOTTOM: 34.46,0.05 34.46,23.84 0.64,23.84 0.64,67.12 0.06,67.12 0.06,72.08 3.62,72.08 3.62,72.71 0.06,72.71 0.06,84.52 3.62,84.52 3.62,85.16 0.06,85.16 0.06,90.12 0.64,90.12 0.64,106.68 121.79,106.68 121.79,39.88 97.15,39.88 97.15,0.64 86.71,0.64 86.71,0.05 81.74,0.05 81.74,3.62 81.11,3.62 81.11,0.05 69.04,0.05 69.04,3.62 68.41,3.62 68.41,0.05 63.42,0.05 63.42,0.64 58.42,0.64 58.42,0.05 53.44,0.05 53.44,3.62 52.81,3.62 52.81,0.05 40.75,0.05 40.75,3.62 40.11,3.62 40.11,0.05 ; 4 cut-outs
GND on L2_GND: 34.46,0.05 34.46,23.84 0.64,23.84 0.64,67.12 0.06,67.12 0.06,72.08 3.62,72.08 3.62,72.71 0.06,72.71 0.06,84.52 3.62,84.52 3.62,85.16 0.06,85.16 0.06,90.12 0.64,90.12 0.64,106.68 121.79,106.68 121.79,39.88 97.15,39.88 97.15,0.64 86.71,0.64 86.71,0.05 81.74,0.05 81.74,3.62 81.11,3.62 81.11,0.05 69.04,0.05 69.04,3.62 68.41,3.62 68.41,0.05 63.42,0.05 63.42,0.64 58.42,0.64 58.42,0.05 53.44,0.05 53.44,3.62 52.81,3.62 52.81,0.05 40.75,0.05 40.75,3.62 40.11,3.62 40.11,0.05
GND on L3_POWER: 87.4,0.05 34.46,0.05 34.46,5.41 87.4,5.41
GND on L3_POWER: 0.05,67.12 0.05,90.12 5.46,90.12 5.46,67.12
GND on L3_POWER: 99.82,41.02 99.82,82.59 98.25,82.58 94.46,82.58 94.46,106.68 121.79,106.68 121.79,83.19 121.79,41.02
GND on L4_GND, L5_GND: 34.46,0.05 34.46,23.84 0.64,23.84 0.64,67.12 0.06,67.12 0.06,90.12 0.64,90.12 0.64,106.68 121.79,106.68 121.79,39.88 97.15,39.88 97.15,0.64 86.71,0.64 86.71,0.05 63.42,0.05 63.42,0.64 58.42,0.64 58.42,0.05
GND2 on TOP: 0.64,0.64 0.64,23.2 20.64,23.2 20.64,22.72 21.01,21.93 21.39,22.72 21.39,23.2 21.73,23.2 22,22.93 22,20.43 22.56,19.87 23.11,20.43 23.11,23.2 25.33,23.2 25.42,23.14 25.4,23.03 24.81,22.44 24.34,22.44 24.34,22.08 24.34,22.08 24.32,21.93 24.34,21.78 24.34,21.77 24.34,21.42 25.53,21.42 25.67,21.36 25.82,21.34 26.94,21.34 27.52,21.93 26.94,22.51 26.14,22.51 26.04,22.58 26.06,22.69 26.58,23.2 33.82,23.2 33.82,0.64 ; 2 cut-outs
GND2 on BOTTOM: 0.64,0.64 0.64,23.2 33.82,23.2 33.82,0.64 ; 1 cut-out
GND2 on L2_GND, L4_GND, L5_GND: 0.64,0.64 0.64,23.2 33.82,23.2 33.82,0.64
LMK_VCC1/5/6 on L3_POWER: 67.69,45.97 67.69,41.05 78.28,41.05 78.28,45.97
V_VCXO3.3 on BOTTOM: 91.57,29.46 91.57,28.45 93.47,28.45 93.47,29.46
V_VCXO3.3 on BOTTOM: 93.47,29.84 93.47,28.07 95.5,28.07 95.5,29.84
V_XO3.3 on BOTTOM: 84.58,18.67 84.58,16.89 86.74,16.89 86.74,18.67
V_XO3.3 on BOTTOM: 82.8,18.41 82.8,17.27 84.58,17.27 84.58,18.41
VA1.8 on TOP: 26.29,26.42 26.29,25.53 27.69,25.53 27.69,26.42
VA3.0 on L3_POWER: 10.15,57.47 10.15,84.67 45.5,84.67 45.5,76.43 26.1,76.43 23.81,74.15 23.81,57.47
VLMK3.3 on L3_POWER: 46.79,51.49 46.79,12.14 47.12,11.81 54.99,11.81 55.5,11.3 81.48,11.3 81.48,51.49 ; 1 cut-out
VSPI1.8 on L3_POWER: 0.64,0.64 0.64,23.2 33.82,23.2 33.82,17.56 13.09,17.56 13.09,0.64
N17168092 on L3_POWER: 13.73,0.64 13.73,16.93 33.82,16.93 33.82,0.64

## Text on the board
BOTTOM: UL94V-0 | BOTTOM SIDE - LAYER 6
Ref Des/Assembly Bottom: K19 | K40 | K1 | A1 | A40 | A19 | ASSEMBLY BOTTOM
Package Geometry/Pastemask Bottom: PASTEMASK BOTTOM
Ref Des/Silkscreen Bottom: J1 | GND2 | GND | SILKSCREEN BOTTOM
User.Comments: SOLDERMASK TOP | SOLDERMASK BOTTOM | ADC14X250 EVM REV A | SEE NOTE 21 | SEE NOTE 19 | SEE NOTE 20 | 19. HOLE SIZE APPLY AFTER PLATING. TOLERANCE TO BE +.001/-.000, DRILL SIZE 60. | 20. HOLE SIZE APPLY AFTER PLATING. TOLERANCE TO BE +.001/-.000, DRILL SIZE 80. | 21. HOLE SIZE TOLERANCE TO BE +.002/-.002, DRILL SIZE 96. | 22. Cu TO THE BOARD EDGES IS INTENTIONAL.
TOP: TOP SIDE - LAYER 1
Ref Des/Assembly Top: ASSEMBLY TOP
Package Geometry/Pastemask Top: PASTEMASK TOP
Ref Des/Silkscreen Top: 1 | STATUS | ADC14X250 | LMK04828 | AUX | ADC14X250EVM REV B | SILKSCREEN TOP
L2_GND: GND 1 - LAYER 2
L3_POWER: PWR PLANE - LAYER 3
L4_GND: GND 2 - LAYER 4
L5_GND: GND 3 - LAYER 5
PLACE_BOUND_BOTTOM: NOTES: | 1. THIS DRAWING IS INTENDED TO HELP IN THE ASSEMBLY OF THE DESIGN. | REFER TO ODB++ FILE FOR SPECIFIC COMPONENT LOCATION INFORMATION. | 2. USE WATER SOLUBLE FLUX DURING BOARD ASSEMBLY. | 3. ASSEMBLY MUST BE RoHS COMPLIANT AND LEAD FREE. | COMPONENT SIDE | SOLDER SIDE | ASSEMBLY DRAWING,
User.10: FIGURE | SIZE | 8.0 | 10.0 | 12.0 | 36.0 | 40.0 | 55.0 | 60.0 | 62.0 | 80.0 | 106.0 | 120.0 | 125.0 | 140.0 | 46.0 | 50.0 | 96.0 | DRILL CHART: TOP to BOTTOM | ALL UNITS ARE IN MILS | PLATED | NON-PLATED | QTY | 30 | 16 | 2239 | 32 | 4 | 20 | 6 | 1 | 2
User.11: 1 | A19 | A40 | A1 | K1 | K19 | K40 | *
User.12: C205 | C206 | J8 | C152 | L14 | L13 | C164 | C204 | C141 | C199 | C160 | C64 | C63 | L8 | Y1 | Y3 | C59 | R31 | Y2 | C57 | R227 | R37 | L5 | L11 | R64 | C103 | L3 | C93 | C117 | C92 | R93 | R92 | R94 | R95 | R113 | C61 | C47 | C118 | R110 | R27 | C4 | C45 | C56 | C5 | C26 | C27 | R73 | R70 | R72 | R77 | C3 | C31 | C87 | R120 | C32 | C14 | C161 | U6 | C16 | Z2 | C126 | C115 | R30 | C201 | C202 | C200 | C203 | C69 | C68 | C71 | C70 | C146 | C136 | C133 | L10 | R54 | R55 | L9 | L4 | L12 | R114 | R61 | R51 | R50 | R43 | R16 | R60 | R76 | R75 | C162 | R71
